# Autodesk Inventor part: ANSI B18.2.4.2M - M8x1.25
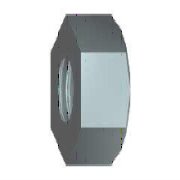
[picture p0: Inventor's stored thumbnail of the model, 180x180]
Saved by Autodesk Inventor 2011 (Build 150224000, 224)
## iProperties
IsCustomPart: 0
Created: 2008-02
Part Number: ANSI B18.2.4.2M - M8x1.25
Material: Steel, Mild
Description: Metric Hex Nuts
Document SubType Name: Modeling
Standard: ANSI B18.2.4.2M
Designer: PN
Standards Organization: ANSI
Language: en-US
Size Designation: M8x1.25
Categories: <MemberInstance><Categories><Category DisplayName="Fasteners" InternalName="e4da775c-781d-43d5-af7c-5136215cf5a6" Mnemonic="FSTN"><Category DisplayName="Nuts" I
Density: 7.86 g/cm^3
Mass: 6.47658 g
Surface Area: 6.89688 cm^2
Volume: 0.823992 cm^3
Author: PN
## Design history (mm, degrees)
sketch "Sketch1"
  geometry: L1 (6.5, 3.753)-(6.5, -3.753); L2 (6.5, -3.753)-(0, -7.506); L3 (0, -7.506)-(-6.5, -3.753); L4 (-6.5, -3.753)-(-6.5, 3.753); L5 (-6.5, 3.753)-(0, 7.506); L6 (0, 7.506)-(6.5, 3.753); C1 r 6.5 at (0, 0); 2 further points
  constraints: 12 end point, 2 coincident, 1 centre point, 1 tangent, 1 vertical, 11 other
  dimensions: "d0" = 13 diameter of C1 (= Smax)
extrude "Extrusion1" new body sketch "Sketch1" distance "d1" = 7.5 (= Mmax); taper "d2" = 0 deg
chamfer "Chamfer1" distance "d10" = 0.625 (= 0.5 x PTC); stored, may be unused: second distance "d11" = 2, angle "d12" = 45 deg
sketch "Sketch3"
  geometry: L1 (-9.171, 0)-(2.529, 0) reference; L2 (-5.705, 0)-(0.857, 0); L3 (-7.5, 0)-(-7.5, -7.506); L4 (-7.5, -7.506)-(0, -7.506); L5 (0, -7.506)-(0, 0); L6 (-7.5, -3.753)-(-7.5, -7.506) reference; L7 (0, -3.753)-(0, -7.506) reference; L8 (0, -7.506)-(-7.5, -7.506) reference; L9 (-7.5, -6.5)-(-6.919, -7.506); L10 (-7.5, -7.506)-(-7.5, -6.5); L11 (-7.5, -7.506)-(-6.919, -7.506); L12 (0, -6.5)-(-0.581, -7.506); L13 (-0.581, -7.506)-(0, -7.506); L14 (0, -7.506)-(0, -6.5)
  constraints: 21 end point, 6 point on line, 5 collinear, 4 vertical, 3 equal length, 2 horizontal
  dimensions: "d32" = 6.5 distance from line of L9.start L1 (= 0.5 x Smax); "d33" = 30 deg angle of L9 L3
revolve "Revolution1" sketch "Sketch3" stored, may be unused: angle "d15" = 90 deg
node "MSC_A1"
node "MSC_PT1"
node "MSC_PT2"
node "MSC_PF1"
body "Solid1"
sketch "Sketch2"
  geometry: L1 (-6.5, 3.753)-(0, 7.506) reference; L2 (0, -7.506)-(-6.5, -3.753) reference; L3 (-6.5, 3.753)-(6.5, -3.753); L4 (-6.5, -3.753)-(6.5, 3.753); 1 further point
  constraints: 4 end point, 2 midpoint, 2 parallel
hole "Hole1" sketch "Sketch2" diameter "d3" = 6.647; stored, may be unused: countersink angle "d7" = 90 deg, drill point angle "d9" = 118 deg; dims "d4" = 6, "d5" = 4, "d6" = 2, "d8" = 8
other parameters: "NND" = 8 [user parameter; used in 1 equation term], "Smax" = 13 [user parameter; used in 2 equation terms], "Mmax" = 7.5 [user parameter; used in 1 equation term], "PTC" = 1.25 [user parameter; used in 1 equation term], "d16" = 0, "d17" = 0, "d18" = 0, "d19" = 0, "d21" = 0, "d22" = 0, "d23" = 0, "THREADDIA" = 8 (= NND) [user parameter], "TEMPLATE" = 12.345 [user parameter]
